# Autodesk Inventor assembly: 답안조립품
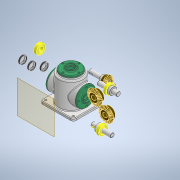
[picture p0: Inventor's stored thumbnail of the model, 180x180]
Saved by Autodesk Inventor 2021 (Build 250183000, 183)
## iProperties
Created: 2021-02
Part Number: 답안조립품
Document SubType Name: Assembly
Designer: 201-12
Author: 201-12
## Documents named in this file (14)
- C:\Users\201-12\Downloads\710214V1003\답안조립품.iam
- C:\Users\201-12\Downloads\710214V1003\본체.ipt
- C:\Users\201-12\Downloads\710214V1003\커버.ipt
- C:\Users\201-12\Downloads\710214V1003\베어링 6203.ipt
- C:\Users\201-12\Downloads\710214V1003\오일 실.ipt
- 오일 실.ipt
- C:\Users\201-12\Downloads\710214V1003\메인 축.ipt
- 메인 축.ipt
- C:\Users\201-12\Downloads\710214V1003\키 5x5.ipt
- C:\Users\201-12\Downloads\710214V1003\메인 베벨기어.ipt
- C:\Users\201-12\Downloads\710214V1003\서브 축.ipt
- 서브 축.ipt
- C:\Users\201-12\Downloads\710214V1003\키 4x4.ipt
- C:\Users\201-12\Downloads\710214V1003\서브 베벨기어.ipt
